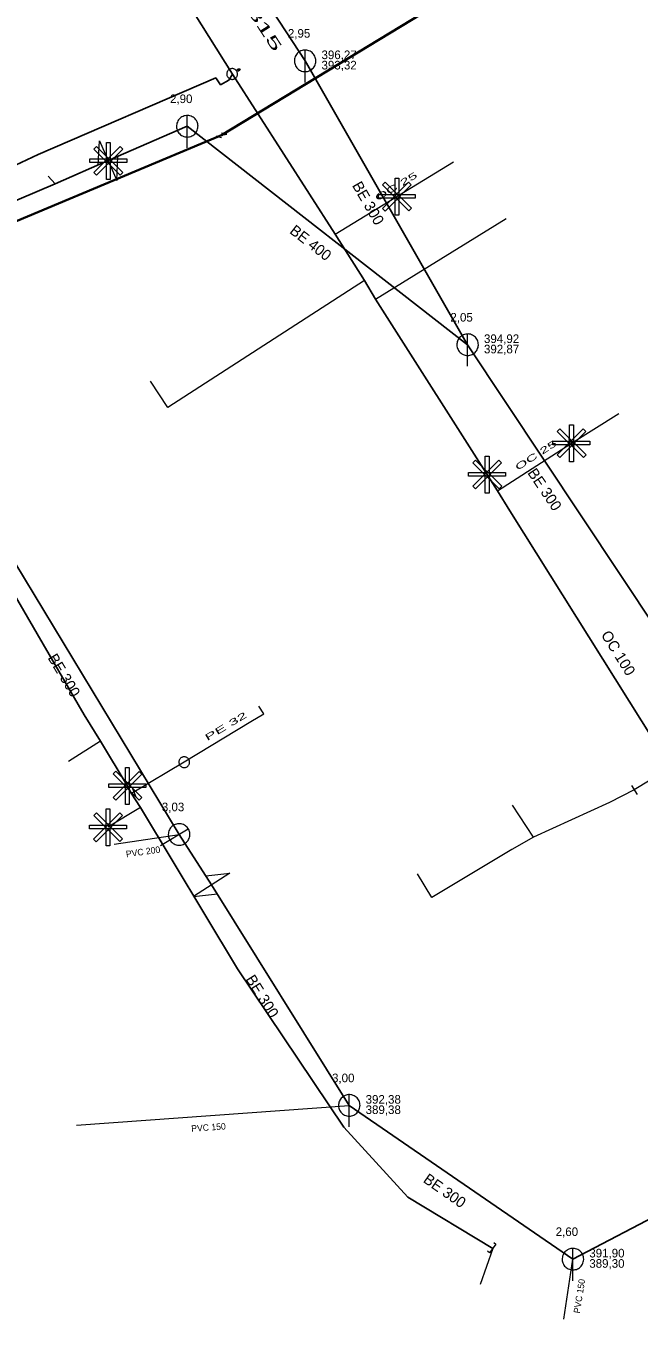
# Model space of a CAD drawing. Extents: x -809028 to -807737, y -990545 to -989489.
# Drawn here: x -808552.3 to -808495.3, y -990076.5 to -989956.3 of the extents above; entities that cross this region are included whole.
import ezdxf

# ---------------------------------------------------------------- set-up
doc = ezdxf.new("R2010")
doc.units = 0
doc.header["$LTSCALE"] = 0.32
for name, color, linetype, lineweight in [('1', 7, 'Continuous', 13), ('10', 7, 'Continuous', 13), ('11', 7, 'Continuous', 13), ('12', 7, 'Continuous', 13), ('13', 7, 'Continuous', 13), ('14', 7, 'Continuous', 25), ('17', 7, 'Continuous', 25), ('22', 7, 'Continuous', 13), ('23', 7, 'Continuous', 13), ('31', 7, 'Continuous', 13), ('34', 7, 'Continuous', 13), ('47', 7, 'Continuous', 13)]:
    doc.layers.add(name, color=color, linetype=linetype, lineweight=lineweight)

msp = doc.modelspace()

# ---------------------------------------------------------------- linework, layer by layer
at = {"layer": '10'}
for points in [[(-808543.543, -989967.482), (-808543.294, -989967.73), (-808545.723, -989970.159), (-808545.97, -989969.911)], [(-808545.962, -989967.721), (-808545.715, -989967.473), (-808543.286, -989969.902), (-808543.532, -989970.15)], [(-808544.809, -989967.118), (-808544.458, -989967.118), (-808544.458, -989970.553), (-808544.809, -989970.553)], [(-808542.924, -989968.627), (-808542.924, -989968.977), (-808546.36, -989968.977), (-808546.36, -989968.627)]]:
    msp.add_lwpolyline(points, close=True, dxfattribs=at)
at = {"layer": '11'}
for p, q in [((-808550.228, -989970.254), (-808549.572, -989970.943)), ((-808544.098, -990032.316), (-808538.055, -990031.421)), ((-808547.58, -990058.434), (-808522.248, -990056.603)), ((-808502.309, -990076.468), (-808501.469, -990070.893))]:
    msp.add_line(p, q, dxfattribs=at)
at = {"layer": '12'}
for points in [[(-808517.994, -989970.441), (-808517.644, -989970.441), (-808517.644, -989973.876), (-808517.994, -989973.876)], [(-808516.728, -989970.805), (-808516.48, -989971.053), (-808518.909, -989973.482), (-808519.156, -989973.234)], [(-808519.147, -989971.044), (-808518.9, -989970.796), (-808516.471, -989973.225), (-808516.718, -989973.473)], [(-808516.11, -989971.95), (-808516.11, -989972.3), (-808519.545, -989972.3), (-808519.545, -989971.95)], [(-808501.773, -989993.359), (-808501.423, -989993.359), (-808501.423, -989996.794), (-808501.773, -989996.794)], [(-808500.507, -989993.723), (-808500.259, -989993.971), (-808502.688, -989996.4), (-808502.934, -989996.152)], [(-808502.926, -989993.962), (-808502.679, -989993.714), (-808500.25, -989996.143), (-808500.497, -989996.391)], [(-808499.889, -989994.868), (-808499.889, -989995.218), (-808503.324, -989995.218), (-808503.324, -989994.868)], [(-808508.34, -989996.637), (-808508.092, -989996.885), (-808510.521, -989999.314), (-808510.767, -989999.066)], [(-808510.759, -989996.876), (-808510.512, -989996.628), (-808508.083, -989999.057), (-808508.33, -989999.305)], [(-808509.606, -989996.273), (-808509.255, -989996.273), (-808509.255, -989999.708), (-808509.606, -989999.708)], [(-808507.722, -989997.782), (-808507.722, -989998.132), (-808511.157, -989998.132), (-808511.157, -989997.782)], [(-808541.763, -990025.56), (-808541.515, -990025.808), (-808543.944, -990028.237), (-808544.191, -990027.989)], [(-808544.182, -990025.799), (-808543.935, -990025.551), (-808541.506, -990027.98), (-808541.753, -990028.228)], [(-808543.029, -990025.196), (-808542.679, -990025.196), (-808542.679, -990028.631), (-808543.029, -990028.631)], [(-808541.145, -990026.705), (-808541.145, -990027.055), (-808544.58, -990027.055), (-808544.58, -990026.705)], [(-808543.567, -990029.419), (-808543.319, -990029.667), (-808545.748, -990032.096), (-808545.995, -990031.848)], [(-808545.986, -990029.658), (-808545.739, -990029.41), (-808543.31, -990031.839), (-808543.557, -990032.087)], [(-808544.833, -990029.055), (-808544.483, -990029.055), (-808544.483, -990032.49), (-808544.833, -990032.49)], [(-808542.949, -990030.564), (-808542.949, -990030.914), (-808546.384, -990030.914), (-808546.384, -990030.564)]]:
    msp.add_lwpolyline(points, close=True, dxfattribs=at)
at = {"layer": '13'}
for p, q in [((-808523.558, -989975.626), (-808512.57, -989968.905)), ((-808519.804, -989981.686), (-808507.669, -989974.19)), ((-808501.615, -989995.044), (-808497.217, -989992.3)), ((-808508.475, -989999.488), (-808501.615, -989995.044)), ((-808545.364, -990022.763), (-808548.335, -990024.647)), ((-808542.26, -990027.471), (-808537.569, -990024.676)), ((-808492.427, -990025.232), (-808495.776, -990027.289)), ((-808541.645, -990028.908), (-808544.677, -990030.741)), ((-808505.127, -990031.675), (-808507.096, -990028.715)), ((-808508.914, -990069.898), (-808510.087, -990073.254))]:
    msp.add_line(p, q, dxfattribs=at)
for points in [[(-808520.82, -989979.929), (-808539.113, -989991.728), (-808540.725, -989989.304)], [(-808537.569, -990024.676), (-808531.396, -990020.934), (-808530.179, -990020.199), (-808530.66, -990019.513)], [(-808495.776, -990027.289), (-808498.074, -990028.441), (-808505.127, -990031.675), (-808507.151, -990032.827), (-808514.587, -990037.267), (-808515.899, -990035.074)]]:
    msp.add_lwpolyline(points, dxfattribs=at)
at = {"layer": '14'}
for p, q in [((-808511.252, -989985.91), (-808493.579, -990012.532)), ((-808501.469, -990070.893), (-808479.357, -990059.274))]:
    msp.add_line(p, q, dxfattribs=at)
at = {"layer": '14', "lineweight": 13}
msp.add_line((-808542.522, -990027.583), (-808542.26, -990027.471), dxfattribs=at)
at = {"layer": '14'}
for points in [[(-808537.236, -989942.856), (-808526.347, -989959.525), (-808511.252, -989985.91)], [(-808544.651, -989968.803), (-808537.298, -989965.604), (-808511.252, -989985.91)], [(-808569.23, -989979.334), (-808549.572, -989970.943), (-808544.651, -989968.803)], [(-808569.23, -989979.334), (-808568.292, -989981.1), (-808559.407, -989995.771), (-808556.033, -990001.675), (-808538.055, -990031.421), (-808535.03, -990036.115), (-808522.248, -990056.603), (-808501.469, -990070.893)]]:
    msp.add_lwpolyline(points, dxfattribs=at)
at = {"layer": '17'}
for points in [[(-808597.027, -989858.141), (-808590.285, -989869.403), (-808588.355, -989872.717), (-808579.785, -989886.311), (-808576.531, -989891.473), (-808571.029, -989900.055), (-808568.32, -989904.55), (-808566.73, -989906.969), (-808565.989, -989908.23), (-808563.671, -989911.931), (-808563.097, -989912.848), (-808553.532, -989928.12), (-808547.531, -989937.702), (-808538.164, -989952.659), (-808533.093, -989960.754)], [(-808533.093, -989960.754), (-808533.43, -989961.315), (-808534.199, -989961.752), (-808534.647, -989961.113), (-808551.155, -989968.217), (-808554.87, -989969.971), (-808572.108, -989977.136)], [(-808533.093, -989960.754), (-808523.558, -989975.626), (-808520.82, -989979.929), (-808519.804, -989981.686), (-808508.475, -989999.488), (-808507.335, -990001.35), (-808493.783, -990022.945), (-808492.427, -990025.232), (-808487.791, -990032.384), (-808480.228, -990044.603), (-808479.217, -990045.69), (-808468.886, -990055.611), (-808464.513, -990059.927), (-808457.57, -990065.789), (-808450.392, -990070.058)], [(-808567.463, -989984.912), (-808564.903, -989989.315), (-808559.226, -989999.059), (-808546.874, -990020.305), (-808545.364, -990022.763), (-808542.872, -990026.881), (-808542.522, -990027.583), (-808541.645, -990028.908), (-808532.624, -990043.916), (-808522.756, -990058.613), (-808516.815, -990065.144), (-808508.914, -990069.898)]]:
    msp.add_lwpolyline(points, dxfattribs=at)
at = {"layer": '17', "lineweight": 35}
for points in [[(-808175.378, -990021.169), (-808177.704, -990021.677), (-808294.901, -989877.126), (-808354.054, -989922.417), (-808417.177, -989916.535), (-808426.857, -989907.375), (-808442.53, -989911.14), (-808444.129, -989911.807), (-808534.115, -989966.436)], [(-808620.873, -990007.571), (-808617.482, -990003.458), (-808605.335, -989996.355), (-808589.077, -989989.493), (-808570.179, -989981.543), (-808534.115, -989966.436)]]:
    msp.add_lwpolyline(points, dxfattribs=at)
at = {"layer": '22'}
for p, q in [((-808526.347, -989961.525), (-808526.346, -989958.525)), ((-808537.298, -989967.604), (-808537.297, -989964.604)), ((-808511.252, -989987.91), (-808511.251, -989984.91)), ((-808539.768, -990032.453), (-808537.198, -990030.905)), ((-808522.248, -990058.603), (-808522.247, -990055.603)), ((-808501.469, -990072.893), (-808501.468, -990069.893))]:
    msp.add_line(p, q, dxfattribs=at)
for points in [[(-808525.347, -989959.525), (-808525.352, -989959.416), (-808525.37, -989959.308), (-808525.4, -989959.202), (-808525.44, -989959.101), (-808525.492, -989959.004), (-808525.554, -989958.914), (-808525.626, -989958.831), (-808525.706, -989958.757), (-808525.794, -989958.691), (-808525.888, -989958.636), (-808525.988, -989958.591), (-808526.093, -989958.558), (-808526.2, -989958.536), (-808526.309, -989958.526), (-808526.419, -989958.528), (-808526.527, -989958.542), (-808526.634, -989958.567), (-808526.737, -989958.604), (-808526.835, -989958.653), (-808526.927, -989958.711), (-808527.013, -989958.78), (-808527.09, -989958.857), (-808527.159, -989958.943), (-808527.218, -989959.035), (-808527.266, -989959.133), (-808527.303, -989959.236), (-808527.329, -989959.343), (-808527.343, -989959.451), (-808527.346, -989959.561), (-808527.336, -989959.67), (-808527.315, -989959.777), (-808527.281, -989959.881), (-808527.237, -989959.981), (-808527.182, -989960.076), (-808527.116, -989960.164), (-808527.042, -989960.244), (-808526.959, -989960.316), (-808526.869, -989960.378), (-808526.773, -989960.43), (-808526.671, -989960.471), (-808526.566, -989960.501), (-808526.458, -989960.519), (-808526.348, -989960.525), (-808526.239, -989960.519), (-808526.131, -989960.501), (-808526.026, -989960.472), (-808525.924, -989960.431), (-808525.827, -989960.379), (-808525.737, -989960.317), (-808525.654, -989960.246), (-808525.579, -989960.166), (-808525.514, -989960.078), (-808525.458, -989959.984), (-808525.414, -989959.884), (-808525.38, -989959.78), (-808525.358, -989959.672), (-808525.348, -989959.563)], [(-808536.298, -989965.604), (-808536.303, -989965.495), (-808536.321, -989965.387), (-808536.351, -989965.281), (-808536.391, -989965.18), (-808536.443, -989965.083), (-808536.505, -989964.993), (-808536.577, -989964.91), (-808536.657, -989964.836), (-808536.745, -989964.77), (-808536.839, -989964.715), (-808536.939, -989964.67), (-808537.044, -989964.637), (-808537.151, -989964.615), (-808537.26, -989964.605), (-808537.37, -989964.607), (-808537.478, -989964.621), (-808537.585, -989964.646), (-808537.688, -989964.683), (-808537.786, -989964.732), (-808537.878, -989964.79), (-808537.964, -989964.859), (-808538.041, -989964.936), (-808538.11, -989965.022), (-808538.169, -989965.114), (-808538.217, -989965.212), (-808538.254, -989965.315), (-808538.28, -989965.422), (-808538.294, -989965.53), (-808538.297, -989965.64), (-808538.287, -989965.749), (-808538.266, -989965.856), (-808538.232, -989965.96), (-808538.188, -989966.06), (-808538.133, -989966.155), (-808538.067, -989966.243), (-808537.993, -989966.323), (-808537.91, -989966.395), (-808537.82, -989966.457), (-808537.724, -989966.509), (-808537.622, -989966.55), (-808537.517, -989966.58), (-808537.409, -989966.598), (-808537.299, -989966.604), (-808537.19, -989966.598), (-808537.082, -989966.58), (-808536.977, -989966.551), (-808536.875, -989966.51), (-808536.778, -989966.458), (-808536.688, -989966.396), (-808536.605, -989966.325), (-808536.53, -989966.245), (-808536.465, -989966.157), (-808536.409, -989966.063), (-808536.365, -989965.963), (-808536.331, -989965.859), (-808536.309, -989965.751), (-808536.299, -989965.642)], [(-808510.252, -989985.91), (-808510.257, -989985.801), (-808510.275, -989985.693), (-808510.305, -989985.587), (-808510.345, -989985.486), (-808510.397, -989985.389), (-808510.459, -989985.299), (-808510.531, -989985.216), (-808510.611, -989985.142), (-808510.699, -989985.076), (-808510.793, -989985.021), (-808510.893, -989984.976), (-808510.998, -989984.943), (-808511.105, -989984.921), (-808511.214, -989984.911), (-808511.324, -989984.913), (-808511.432, -989984.927), (-808511.539, -989984.952), (-808511.642, -989984.989), (-808511.74, -989985.038), (-808511.832, -989985.096), (-808511.918, -989985.165), (-808511.995, -989985.242), (-808512.064, -989985.328), (-808512.123, -989985.42), (-808512.171, -989985.518), (-808512.208, -989985.621), (-808512.234, -989985.728), (-808512.248, -989985.836), (-808512.251, -989985.946), (-808512.241, -989986.055), (-808512.22, -989986.162), (-808512.186, -989986.266), (-808512.142, -989986.366), (-808512.087, -989986.461), (-808512.021, -989986.549), (-808511.947, -989986.629), (-808511.864, -989986.701), (-808511.774, -989986.763), (-808511.678, -989986.815), (-808511.576, -989986.856), (-808511.471, -989986.886), (-808511.363, -989986.904), (-808511.253, -989986.91), (-808511.144, -989986.904), (-808511.036, -989986.886), (-808510.931, -989986.857), (-808510.829, -989986.816), (-808510.732, -989986.764), (-808510.642, -989986.702), (-808510.559, -989986.631), (-808510.484, -989986.551), (-808510.419, -989986.463), (-808510.363, -989986.369), (-808510.319, -989986.269), (-808510.285, -989986.165), (-808510.263, -989986.057), (-808510.253, -989985.948)], [(-808537.539, -990032.277), (-808537.449, -990032.216), (-808537.365, -990032.145), (-808537.29, -990032.064), (-808537.224, -990031.978), (-808537.168, -990031.883), (-808537.123, -990031.784), (-808537.089, -990031.679), (-808537.067, -990031.573), (-808537.056, -990031.463), (-808537.057, -990031.354), (-808537.07, -990031.245), (-808537.096, -990031.138), (-808537.132, -990031.035), (-808537.18, -990030.937), (-808537.239, -990030.844), (-808537.306, -990030.758), (-808537.383, -990030.68), (-808537.468, -990030.61), (-808537.56, -990030.552), (-808537.658, -990030.503), (-808537.761, -990030.465), (-808537.867, -990030.439), (-808537.976, -990030.424), (-808538.085, -990030.421), (-808538.194, -990030.43), (-808538.301, -990030.452), (-808538.406, -990030.485), (-808538.506, -990030.529), (-808538.601, -990030.584), (-808538.69, -990030.649), (-808538.77, -990030.722), (-808538.842, -990030.805), (-808538.905, -990030.894), (-808538.958, -990030.99), (-808538.999, -990031.092), (-808539.029, -990031.197), (-808539.048, -990031.305), (-808539.055, -990031.414), (-808539.05, -990031.523), (-808539.032, -990031.632), (-808539.004, -990031.737), (-808538.964, -990031.839), (-808538.912, -990031.936), (-808538.851, -990032.026), (-808538.779, -990032.11), (-808538.7, -990032.184), (-808538.613, -990032.251), (-808538.518, -990032.307), (-808538.418, -990032.352), (-808538.315, -990032.386), (-808538.208, -990032.409), (-808538.099, -990032.42), (-808537.989, -990032.419), (-808537.881, -990032.405), (-808537.774, -990032.381), (-808537.67, -990032.344), (-808537.572, -990032.296)], [(-808521.248, -990056.603), (-808521.253, -990056.494), (-808521.271, -990056.386), (-808521.301, -990056.28), (-808521.341, -990056.179), (-808521.393, -990056.082), (-808521.455, -990055.992), (-808521.527, -990055.909), (-808521.607, -990055.835), (-808521.695, -990055.769), (-808521.789, -990055.714), (-808521.889, -990055.669), (-808521.994, -990055.636), (-808522.101, -990055.614), (-808522.21, -990055.604), (-808522.32, -990055.606), (-808522.428, -990055.62), (-808522.535, -990055.645), (-808522.638, -990055.682), (-808522.736, -990055.731), (-808522.828, -990055.789), (-808522.914, -990055.858), (-808522.991, -990055.935), (-808523.06, -990056.021), (-808523.119, -990056.113), (-808523.167, -990056.211), (-808523.204, -990056.314), (-808523.23, -990056.421), (-808523.244, -990056.529), (-808523.247, -990056.639), (-808523.237, -990056.748), (-808523.216, -990056.855), (-808523.182, -990056.959), (-808523.138, -990057.059), (-808523.083, -990057.154), (-808523.017, -990057.242), (-808522.943, -990057.322), (-808522.86, -990057.394), (-808522.77, -990057.456), (-808522.674, -990057.508), (-808522.572, -990057.549), (-808522.467, -990057.579), (-808522.359, -990057.597), (-808522.249, -990057.603), (-808522.14, -990057.597), (-808522.032, -990057.579), (-808521.927, -990057.55), (-808521.825, -990057.509), (-808521.728, -990057.457), (-808521.638, -990057.395), (-808521.555, -990057.324), (-808521.48, -990057.244), (-808521.415, -990057.156), (-808521.359, -990057.062), (-808521.315, -990056.962), (-808521.281, -990056.858), (-808521.259, -990056.75), (-808521.249, -990056.641)], [(-808500.469, -990070.893), (-808500.474, -990070.784), (-808500.492, -990070.676), (-808500.522, -990070.57), (-808500.562, -990070.469), (-808500.614, -990070.372), (-808500.676, -990070.282), (-808500.748, -990070.199), (-808500.828, -990070.125), (-808500.916, -990070.059), (-808501.01, -990070.004), (-808501.11, -990069.959), (-808501.215, -990069.926), (-808501.322, -990069.904), (-808501.431, -990069.894), (-808501.541, -990069.896), (-808501.649, -990069.91), (-808501.756, -990069.935), (-808501.859, -990069.972), (-808501.957, -990070.021), (-808502.049, -990070.079), (-808502.135, -990070.148), (-808502.212, -990070.225), (-808502.281, -990070.311), (-808502.34, -990070.403), (-808502.388, -990070.501), (-808502.425, -990070.604), (-808502.451, -990070.711), (-808502.465, -990070.819), (-808502.468, -990070.929), (-808502.458, -990071.038), (-808502.437, -990071.145), (-808502.403, -990071.249), (-808502.359, -990071.349), (-808502.304, -990071.444), (-808502.238, -990071.532), (-808502.164, -990071.612), (-808502.081, -990071.684), (-808501.991, -990071.746), (-808501.895, -990071.798), (-808501.793, -990071.839), (-808501.688, -990071.869), (-808501.58, -990071.887), (-808501.47, -990071.893), (-808501.361, -990071.887), (-808501.253, -990071.869), (-808501.148, -990071.84), (-808501.046, -990071.799), (-808500.949, -990071.747), (-808500.859, -990071.685), (-808500.776, -990071.614), (-808500.701, -990071.534), (-808500.636, -990071.446), (-808500.58, -990071.352), (-808500.536, -990071.252), (-808500.502, -990071.148), (-808500.48, -990071.04), (-808500.47, -990070.931)]]:
    msp.add_lwpolyline(points, close=True, dxfattribs=at)
at = {"layer": '23'}
msp.add_line((-808532.506, -989960.466), (-808532.615, -989960.303), dxfattribs=at)
for points in [[(-808532.843, -989961.16), (-808532.8, -989961.128), (-808532.762, -989961.092), (-808532.729, -989961.052), (-808532.699, -989961.009), (-808532.674, -989960.964), (-808532.654, -989960.914), (-808532.639, -989960.865), (-808532.63, -989960.814), (-808532.625, -989960.762), (-808532.626, -989960.709), (-808532.632, -989960.657), (-808532.645, -989960.605), (-808532.662, -989960.557), (-808532.684, -989960.51), (-808532.711, -989960.465), (-808532.744, -989960.423), (-808532.778, -989960.385), (-808532.82, -989960.351), (-808532.861, -989960.321), (-808532.907, -989960.296), (-808532.957, -989960.276), (-808533.007, -989960.261), (-808533.059, -989960.251), (-808533.11, -989960.246), (-808533.162, -989960.248), (-808533.215, -989960.256), (-808533.265, -989960.267), (-808533.314, -989960.285), (-808533.361, -989960.308), (-808533.406, -989960.334), (-808533.448, -989960.365), (-808533.486, -989960.402), (-808533.521, -989960.442), (-808533.55, -989960.484), (-808533.574, -989960.53), (-808533.594, -989960.578), (-808533.61, -989960.629), (-808533.62, -989960.681), (-808533.624, -989960.733)], [(-808532.82, -989960.351), (-808532.861, -989960.321), (-808532.907, -989960.296), (-808532.957, -989960.276), (-808533.007, -989960.261), (-808533.059, -989960.251), (-808533.11, -989960.246), (-808533.162, -989960.248), (-808533.215, -989960.256), (-808533.265, -989960.267), (-808533.314, -989960.285), (-808533.361, -989960.308), (-808533.406, -989960.334), (-808533.448, -989960.365), (-808533.486, -989960.402), (-808533.521, -989960.442), (-808533.55, -989960.484), (-808533.574, -989960.53), (-808533.594, -989960.578), (-808533.61, -989960.629), (-808533.62, -989960.681), (-808533.624, -989960.733), (-808533.623, -989960.784), (-808533.616, -989960.837), (-808533.605, -989960.887), (-808533.586, -989960.937), (-808533.564, -989960.983), (-808533.537, -989961.028), (-808533.505, -989961.069), (-808533.47, -989961.108), (-808533.43, -989961.143), (-808533.386, -989961.172), (-808533.34, -989961.198), (-808533.293, -989961.218), (-808533.242, -989961.232), (-808533.191, -989961.242), (-808533.14, -989961.246), (-808533.086, -989961.246), (-808533.034, -989961.239), (-808532.983, -989961.226)], [(-808533.624, -989960.733), (-808533.623, -989960.784), (-808533.616, -989960.837), (-808533.605, -989960.887), (-808533.586, -989960.937), (-808533.564, -989960.983), (-808533.537, -989961.028), (-808533.505, -989961.069), (-808533.47, -989961.108), (-808533.43, -989961.143), (-808533.386, -989961.172), (-808533.34, -989961.198), (-808533.293, -989961.218), (-808533.242, -989961.232), (-808533.191, -989961.242), (-808533.14, -989961.246), (-808533.086, -989961.246), (-808533.034, -989961.239), (-808532.983, -989961.226), (-808532.934, -989961.208), (-808532.887, -989961.186), (-808532.843, -989961.16), (-808532.8, -989961.128), (-808532.762, -989961.092), (-808532.729, -989961.052), (-808532.699, -989961.009), (-808532.674, -989960.964), (-808532.654, -989960.914), (-808532.639, -989960.865), (-808532.63, -989960.814), (-808532.625, -989960.762), (-808532.626, -989960.709), (-808532.632, -989960.657), (-808532.645, -989960.605), (-808532.662, -989960.557), (-808532.684, -989960.51), (-808532.711, -989960.465), (-808532.744, -989960.423), (-808532.778, -989960.385), (-808532.82, -989960.351)], [(-808532.695, -989960.357), (-808532.571, -989960.274), (-808532.391, -989960.273), (-808532.463, -989960.437), (-808532.587, -989960.52)], [(-808532.983, -989961.226), (-808532.934, -989961.208), (-808532.887, -989961.186), (-808532.843, -989961.16)], [(-808537.15, -990024.446), (-808537.179, -990024.402), (-808537.214, -990024.362), (-808537.252, -990024.328), (-808537.293, -990024.296), (-808537.337, -990024.268), (-808537.386, -990024.246), (-808537.434, -990024.228), (-808537.485, -990024.216), (-808537.537, -990024.209), (-808537.589, -990024.207), (-808537.642, -990024.211), (-808537.694, -990024.221), (-808537.743, -990024.235), (-808537.791, -990024.256), (-808537.837, -990024.28), (-808537.881, -990024.311), (-808537.92, -990024.343), (-808537.957, -990024.383), (-808537.988, -990024.422), (-808538.016, -990024.467), (-808538.038, -990024.516), (-808538.056, -990024.565), (-808538.068, -990024.616), (-808538.076, -990024.668), (-808538.077, -990024.719), (-808538.072, -990024.772), (-808538.063, -990024.823), (-808538.048, -990024.873), (-808538.027, -990024.921), (-808538.003, -990024.968), (-808537.974, -990025.011), (-808537.94, -990025.051), (-808537.902, -990025.087), (-808537.861, -990025.119), (-808537.816, -990025.145), (-808537.769, -990025.168), (-808537.719, -990025.186), (-808537.668, -990025.199), (-808537.616, -990025.205)], [(-808537.957, -990024.383), (-808537.988, -990024.422), (-808538.016, -990024.467), (-808538.038, -990024.516), (-808538.056, -990024.565), (-808538.068, -990024.616), (-808538.076, -990024.668), (-808538.077, -990024.719), (-808538.072, -990024.772), (-808538.063, -990024.823), (-808538.048, -990024.873), (-808538.027, -990024.921), (-808538.003, -990024.968), (-808537.974, -990025.011), (-808537.94, -990025.051), (-808537.902, -990025.087), (-808537.861, -990025.119), (-808537.816, -990025.145), (-808537.769, -990025.168), (-808537.719, -990025.186), (-808537.668, -990025.199), (-808537.616, -990025.205), (-808537.565, -990025.207), (-808537.512, -990025.202), (-808537.461, -990025.194), (-808537.41, -990025.178), (-808537.363, -990025.158), (-808537.317, -990025.134), (-808537.274, -990025.104), (-808537.233, -990025.07), (-808537.197, -990025.032), (-808537.166, -990024.99), (-808537.138, -990024.946), (-808537.115, -990024.899), (-808537.099, -990024.849), (-808537.085, -990024.799), (-808537.079, -990024.747), (-808537.077, -990024.694), (-808537.081, -990024.642), (-808537.091, -990024.591)], [(-808537.616, -990025.205), (-808537.565, -990025.207), (-808537.512, -990025.202), (-808537.461, -990025.194), (-808537.41, -990025.178), (-808537.363, -990025.158), (-808537.317, -990025.134), (-808537.274, -990025.104), (-808537.233, -990025.07), (-808537.197, -990025.032), (-808537.166, -990024.99), (-808537.138, -990024.946), (-808537.115, -990024.899), (-808537.099, -990024.849), (-808537.085, -990024.799), (-808537.079, -990024.747), (-808537.077, -990024.694), (-808537.081, -990024.642), (-808537.091, -990024.591), (-808537.106, -990024.541), (-808537.126, -990024.493), (-808537.15, -990024.446), (-808537.179, -990024.402), (-808537.214, -990024.362), (-808537.252, -990024.328), (-808537.293, -990024.296), (-808537.337, -990024.268), (-808537.386, -990024.246), (-808537.434, -990024.228), (-808537.485, -990024.216), (-808537.537, -990024.209), (-808537.589, -990024.207), (-808537.642, -990024.211), (-808537.694, -990024.221), (-808537.743, -990024.235), (-808537.791, -990024.256), (-808537.837, -990024.28), (-808537.881, -990024.311), (-808537.92, -990024.343), (-808537.957, -990024.383)], [(-808537.091, -990024.591), (-808537.106, -990024.541), (-808537.126, -990024.493), (-808537.15, -990024.446)]]:
    msp.add_lwpolyline(points, dxfattribs=at)
at = {"layer": '31'}
for points in [[(-808545.567, -989969.202), (-808545.448, -989966.969), (-808543.852, -989970.637), (-808543.733, -989968.404)], [(-808535.572, -990035.274), (-808533.349, -990035.031), (-808536.711, -990037.198), (-808534.488, -990036.955)]]:
    msp.add_lwpolyline(points, dxfattribs=at)
at = {"layer": '34'}
for p, q in [((-808501.887, -989994.624), (-808501.343, -989995.463)), ((-808542.456, -990027.011), (-808542.064, -990027.931)), ((-808496.04, -990026.864), (-808495.511, -990027.713))]:
    msp.add_line(p, q, dxfattribs=at)
at = {"layer": '47'}
msp.add_line((-808534.615, -989966.533), (-808534.115, -989966.637), dxfattribs=at)
for points in [[(-808534.615, -989966.533), (-808533.614, -989966.338), (-808534.114, -989966.235)], [(-808508.822, -990069.349), (-808508.619, -990069.498), (-808509.208, -990070.297), (-808509.411, -990070.147)]]:
    msp.add_lwpolyline(points, dxfattribs=at)

# ---------------------------------------------------------------- texts
at = {"layer": '1'}
for s, height, rotation, width, p in [('PVC 315 ', 1, 303, 2.1, (-808535.367, -989949.346)), ('OC 25 ', 0.6, 31, 1.9, (-808519.626, -989972.586)), ('OC 25 ', 0.6, 33, 1.9, (-808506.597, -989997.627)), ('PE 32 ', 0.6, 31, 2, (-808535.438, -990022.749))]:
    msp.add_text(s, height=height, rotation=rotation, dxfattribs=dict(at, width=width)).set_placement(p)
for s, p in [('2,95', (-808527.947, -989957.373)), ('2,90', (-808538.898, -989963.452)), ('2,05', (-808512.852, -989983.758)), ('3,03', (-808539.655, -990029.268)), ('3,00', (-808523.848, -990054.451)), ('2,60', (-808503.069, -990068.741))]:
    msp.add_text(s, height=0.8, dxfattribs=at).set_placement(p)
for s, height, rotation, p in [('BE 300', 1, 300, (-808522.012, -989971.099)), ('BE 400', 1, 322, (-808527.861, -989975.478)), ('BE 300', 1, 304, (-808505.728, -989997.82)), ('OC 100', 1, 302, (-808498.895, -990012.871)), ('BE 300', 1, 301, (-808550.294, -990015.007)), ('PVC 200 ', 0.6, 8, (-808542.95, -990033.551)), ('BE 300', 1, 302, (-808531.911, -990044.864)), ('PVC 150 ', 0.6, 4, (-808536.907, -990059.057)), ('BE 300', 1, 325, (-808515.455, -990063.683)), ('PVC 150 ', 0.6, 81, (-808500.826, -990075.964))]:
    msp.add_text(s, height=height, rotation=rotation, dxfattribs=at).set_placement(p)
at = {"layer": '14'}
for s, p in [('396,27', (-808524.825, -989959.365)), ('393,32', (-808524.825, -989960.325)), ('394,92', (-808509.731, -989985.75)), ('392,87', (-808509.731, -989986.71)), ('392,38', (-808520.726, -990056.443)), ('389,38', (-808520.726, -990057.403)), ('391,90', (-808499.947, -990070.733)), ('389,30', (-808499.947, -990071.693))]:
    msp.add_text(s, height=0.8, dxfattribs=at).set_placement(p)

doc.saveas('drawing.dxf')
